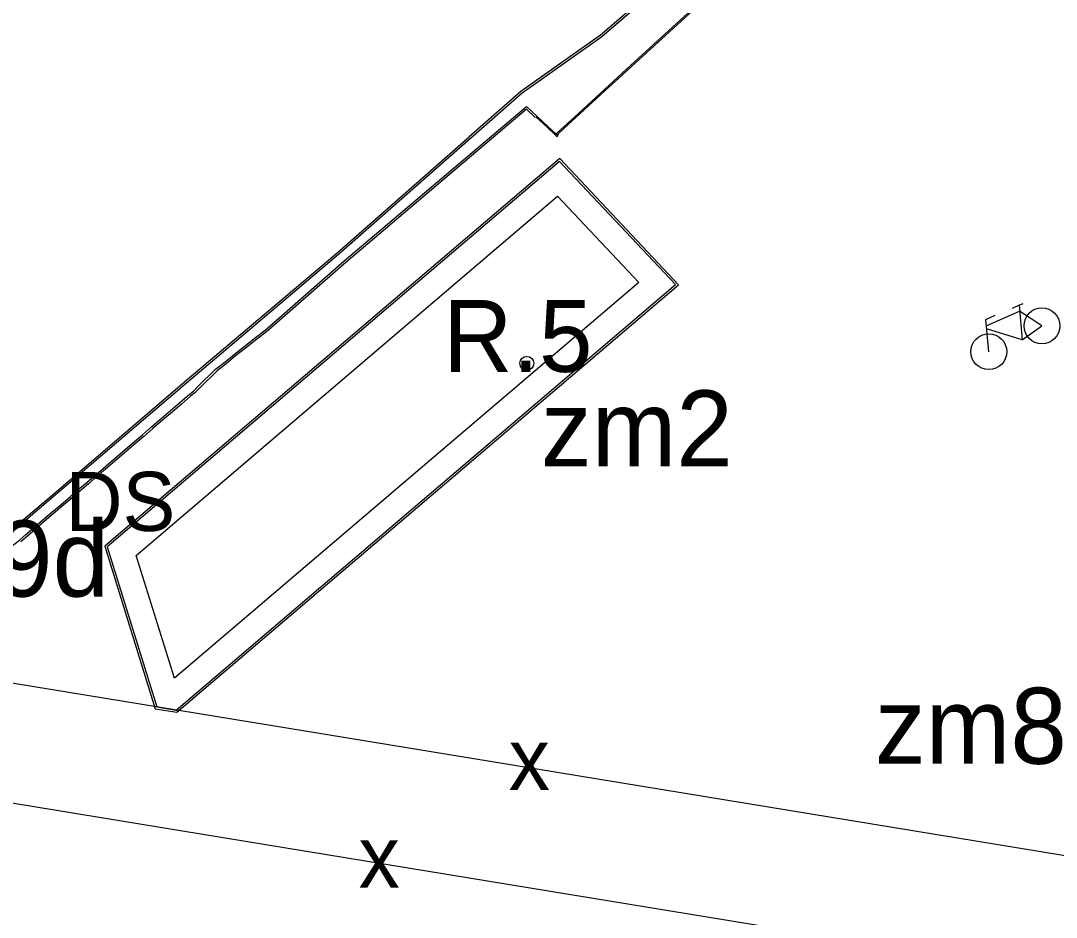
# Model space of a CAD drawing. Extents: x -555070 to -553076, y -1186731 to -1182766.
# Drawn here: x -554659.4 to -554414.1, y -1185500.5 to -1185288.2 of the extents above; entities that cross this region are included whole.
import ezdxf

# ---------------------------------------------------------------- set-up
doc = ezdxf.new("R2010")
doc.units = 0
for name, color, linetype in [('CYKLISTI_stav', 7, 'Continuous'), ('HRANICE_ZMENY_DO_KOO', 7, 'Continuous'), ('Level 10', 7, 'Continuous'), ('Level 13', 7, 'Continuous'), ('Level 29', 7, 'Continuous'), ('Level 4', 7, 'Continuous'), ('Level 46', 7, 'Continuous'), ('Level 59', 7, 'Continuous'), ('OBRYS_PLOCH', 7, 'Continuous'), ('rezerva_BV', 7, 'Continuous'), ('stav_DS', 7, 'Continuous')]:
    doc.layers.add(name, color=color, linetype=linetype)

msp = doc.modelspace()

# ---------------------------------------------------------------- linework, layer by layer
at = {"layer": 'CYKLISTI_stav'}
for p, q in [((-554422.93, -1185355.56), (-554424.57, -1185356.33)), ((-554422.93, -1185355.56), (-554422.02, -1185355.16)), ((-554422.93, -1185355.56), (-554422.24, -1185363.73)), ((-554430.86, -1185358.95), (-554428.64, -1185357.93)), ((-554430.13, -1185366.55), (-554430.86, -1185358.95)), ((-554430.72, -1185360.44), (-554422.82, -1185356.93)), ((-554417.54, -1185360.43), (-554422.82, -1185356.93)), ((-554422.24, -1185363.73), (-554430.65, -1185361.15)), ((-554422.24, -1185363.73), (-554417.54, -1185360.43))]:
    msp.add_line(p, q, dxfattribs=at)
for centre in [(-554417.54, -1185360.43), (-554430.13, -1185366.55)]:
    msp.add_circle(centre, 4.25, dxfattribs=at)
at = {"layer": 'HRANICE_ZMENY_DO_KOO'}
for p, q in [((-554497.69, -1185270.65), (-554522.05, -1185291.6)), ((-554522.05, -1185291.6), (-554540.91, -1185304.97)), ((-554540.91, -1185304.97), (-554553.18, -1185315.71)), ((-554539.64, -1185309.13), (-554582.42, -1185345.45)), ((-554537.54, -1185311.08), (-554539.64, -1185309.13)), ((-554584.48, -1185343.12), (-554553.18, -1185315.71)), ((-554620.48, -1185373.63), (-554584.48, -1185343.12)), ((-554582.42, -1185345.45), (-554601.2, -1185361.87)), ((-554603.5, -1185363.59), (-554606.15, -1185365.72)), ((-554601.2, -1185361.87), (-554603.5, -1185363.59)), ((-554606.15, -1185365.72), (-554608.48, -1185367.51)), ((-554608.48, -1185367.51), (-554610.74, -1185369.4)), ((-554612.89, -1185371.08), (-554616.97, -1185375.08)), ((-554610.74, -1185369.4), (-554612.89, -1185371.08)), ((-554650.96, -1185399.7), (-554620.48, -1185373.63)), ((-554618.16, -1185376.25), (-554619.15, -1185377.1)), ((-554616.97, -1185375.08), (-554618.16, -1185376.25)), ((-554619.15, -1185377.1), (-554621.34, -1185378.97)), ((-554623.55, -1185380.87), (-554625.78, -1185382.78)), ((-554621.34, -1185378.97), (-554623.55, -1185380.87)), ((-554625.78, -1185382.78), (-554628.06, -1185384.72)), ((-554628.06, -1185384.72), (-554630.26, -1185386.6)), ((-554632.58, -1185388.59), (-554634.89, -1185390.58)), ((-554630.26, -1185386.6), (-554632.58, -1185388.59)), ((-554634.89, -1185390.58), (-554638.83, -1185393.94)), ((-554638.83, -1185393.94), (-554641.3, -1185396.06)), ((-554643.35, -1185397.82), (-554645.42, -1185399.59)), ((-554641.3, -1185396.06), (-554643.35, -1185397.82)), ((-554662.18, -1185409.19), (-554650.96, -1185399.7)), ((-554645.42, -1185399.59), (-554647.3, -1185401.2)), ((-554649.6, -1185403.16), (-554651.7, -1185404.96)), ((-554647.3, -1185401.2), (-554649.6, -1185403.16)), ((-554651.7, -1185404.96), (-554653.79, -1185406.76)), ((-554653.79, -1185406.76), (-554655.81, -1185408.47)), ((-554657.81, -1185410.19), (-554659.38, -1185411.54)), ((-554655.81, -1185408.47), (-554657.81, -1185410.19))]:
    msp.add_line(p, q, dxfattribs=at)
msp.add_lwpolyline([(-554537.4, -1185310.93), (-554534.73, -1185313.41), (-554532.82, -1185315.19), (-554532.31, -1185315.67), (-554532.05, -1185314.87), (-554529.73, -1185312.74), (-554527.04, -1185310.28), (-554524.01, -1185307.5), (-554520.98, -1185304.73), (-554517.74, -1185301.76), (-554514.76, -1185299.04), (-554501.19, -1185286.63), (-554500.05, -1185285.59), (-554483.01, -1185271.32), (-554467.44, -1185258.63), (-554452.63, -1185246.62), (-554445.86, -1185240.54), (-554433.11, -1185229.16), (-554430.24, -1185228.1), (-554425.89, -1185227.65), (-554422.67, -1185227.83), (-554416.8, -1185229.06), (-554414.23, -1185229.78)], dxfattribs=at)
msp.add_lwpolyline([(-554503.58, -1185350.68), (-554531.74, -1185320.8), (-554639.5, -1185412.62), (-554627.57, -1185451.08), (-554622.41, -1185451.92)], close=True, dxfattribs=at)
at = {"layer": 'Level 13'}
for p, q in [((-554531.78, -1185321.49), (-554638.92, -1185412.79)), ((-554504.31, -1185350.64), (-554531.78, -1185321.49)), ((-554622.56, -1185451.39), (-554504.31, -1185350.64))]:
    msp.add_line(p, q, dxfattribs=at)
msp.add_lwpolyline([(-554638.92, -1185412.79), (-554627.18, -1185450.64), (-554622.56, -1185451.39)], dxfattribs=at)
at = {"layer": 'Level 29'}
for points in [[(-554293.2, -1185505.39), (-554587.17, -1185457.18), (-554869.52, -1185410.99), (-555057.83, -1185309.87), (-555060.53, -1185308.42)], [(-555065.37, -1185337.55), (-554878.61, -1185437.76), (-554591.7, -1185484.82), (-554218.96, -1185545.93), (-553901.49, -1185597.94), (-553620.76, -1185643.99), (-553313.81, -1185694.25), (-553085.95, -1185731.63)]]:
    msp.add_lwpolyline(points, dxfattribs=at)
at = {"layer": 'Level 4'}
msp.add_circle((-554539.54, -1185369.3), 1.64, dxfattribs=at)
at = {"layer": 'OBRYS_PLOCH'}
for p, q in [((-554521.74, -1185291.99), (-554540.6, -1185305.36)), ((-554582.75, -1185345.07), (-554539.62, -1185308.46)), ((-554539.62, -1185308.46), (-554537.2, -1185310.71)), ((-554537.2, -1185310.71), (-554534.53, -1185313.19)), ((-554534.53, -1185313.19), (-554532.62, -1185314.97)), ((-554532.62, -1185314.97), (-554532.45, -1185315.13)), ((-554601.51, -1185361.48), (-554582.75, -1185345.07)), ((-554603.81, -1185363.19), (-554601.51, -1185361.48)), ((-554613.22, -1185370.7), (-554611.05, -1185369.01)), ((-554621.67, -1185378.59), (-554619.48, -1185376.72)), ((-554635.22, -1185390.2), (-554632.91, -1185388.21)), ((-554639.15, -1185393.56), (-554635.22, -1185390.2)), ((-554641.63, -1185395.68), (-554639.15, -1185393.56)), ((-554649.92, -1185402.78), (-554647.63, -1185400.82)), ((-554647.63, -1185400.82), (-554645.75, -1185399.21))]:
    msp.add_line(p, q, dxfattribs=at)
for points in [[(-554468.69, -1185246.34), (-554489.84, -1185263.62), (-554497.35, -1185271.02), (-554521.74, -1185291.99)], [(-554532.45, -1185315.13), (-554532.31, -1185314.7), (-554529.93, -1185312.52), (-554527.24, -1185310.06), (-554524.21, -1185307.28), (-554521.18, -1185304.51), (-554517.94, -1185301.54), (-554514.96, -1185298.82), (-554501.39, -1185286.41), (-554500.25, -1185285.36), (-554483.2, -1185271.09)], [(-554540.6, -1185305.36), (-554552.85, -1185316.09), (-554584.15, -1185343.5), (-554620.16, -1185374.01)], [(-554611.05, -1185369.01), (-554608.79, -1185367.12), (-554606.46, -1185365.33), (-554603.81, -1185363.19)], [(-554619.48, -1185376.72), (-554618.5, -1185375.88), (-554617.32, -1185374.72), (-554613.22, -1185370.7)], [(-554620.16, -1185374.01), (-554650.64, -1185400.08), (-554661.85, -1185409.57)], [(-554626.11, -1185382.4), (-554623.88, -1185380.49), (-554621.67, -1185378.59)], [(-554632.91, -1185388.21), (-554630.58, -1185386.22), (-554628.38, -1185384.34), (-554626.11, -1185382.4)], [(-554645.75, -1185399.21), (-554643.68, -1185397.44), (-554641.63, -1185395.68)], [(-554654.12, -1185406.38), (-554652.03, -1185404.58), (-554649.92, -1185402.78)], [(-554658.14, -1185409.81), (-554656.13, -1185408.09), (-554654.12, -1185406.38)], [(-554663.8, -1185414.32), (-554661.71, -1185412.73), (-554659.7, -1185411.15), (-554658.14, -1185409.81)]]:
    msp.add_lwpolyline(points, dxfattribs=at)
at = {"layer": 'rezerva_BV'}
for p, q in [((-554531.78, -1185321.49), (-554638.92, -1185412.79)), ((-554531.78, -1185321.49), (-554638.92, -1185412.79)), ((-554504.31, -1185350.64), (-554531.78, -1185321.49)), ((-554504.31, -1185350.64), (-554531.78, -1185321.49)), ((-554622.56, -1185451.39), (-554504.31, -1185350.64)), ((-554622.56, -1185451.39), (-554504.31, -1185350.64))]:
    msp.add_line(p, q, dxfattribs=at)
for points in [[(-554622.99, -1185443.89), (-554632.02, -1185414.79), (-554532.23, -1185329.76), (-554513, -1185350.16), (-554622.99, -1185443.89)], [(-554638.92, -1185412.79), (-554627.18, -1185450.64), (-554622.56, -1185451.39)], [(-554638.92, -1185412.79), (-554627.18, -1185450.64), (-554622.56, -1185451.39)]]:
    msp.add_lwpolyline(points, dxfattribs=at)
at = {"layer": 'stav_DS'}
for p, q in [((-554521.74, -1185291.99), (-554540.6, -1185305.36)), ((-554582.75, -1185345.07), (-554539.62, -1185308.46)), ((-554539.62, -1185308.46), (-554537.2, -1185310.71)), ((-554537.2, -1185310.71), (-554534.53, -1185313.19)), ((-554534.53, -1185313.19), (-554532.62, -1185314.97)), ((-554532.62, -1185314.97), (-554532.45, -1185315.13)), ((-554601.51, -1185361.48), (-554582.75, -1185345.07)), ((-554603.81, -1185363.19), (-554601.51, -1185361.48)), ((-554613.22, -1185370.7), (-554611.05, -1185369.01)), ((-554621.67, -1185378.59), (-554619.48, -1185376.72)), ((-554635.22, -1185390.2), (-554632.91, -1185388.21)), ((-554639.15, -1185393.56), (-554635.22, -1185390.2)), ((-554641.63, -1185395.68), (-554639.15, -1185393.56)), ((-554649.92, -1185402.78), (-554647.63, -1185400.82)), ((-554647.63, -1185400.82), (-554645.75, -1185399.21))]:
    msp.add_line(p, q, dxfattribs=at)
for points in [[(-554468.69, -1185246.34), (-554489.84, -1185263.62), (-554497.35, -1185271.02), (-554521.74, -1185291.99)], [(-554532.45, -1185315.13), (-554532.31, -1185314.7), (-554529.93, -1185312.52), (-554527.24, -1185310.06), (-554524.21, -1185307.28), (-554521.18, -1185304.51), (-554517.94, -1185301.54), (-554514.96, -1185298.82), (-554501.39, -1185286.41), (-554500.25, -1185285.36), (-554483.2, -1185271.09)], [(-554540.6, -1185305.36), (-554552.85, -1185316.09), (-554584.15, -1185343.5), (-554620.16, -1185374.01)], [(-554611.05, -1185369.01), (-554608.79, -1185367.12), (-554606.46, -1185365.33), (-554603.81, -1185363.19)], [(-554619.48, -1185376.72), (-554618.5, -1185375.88), (-554617.32, -1185374.72), (-554613.22, -1185370.7)], [(-554620.16, -1185374.01), (-554650.64, -1185400.08), (-554661.85, -1185409.57)], [(-554626.11, -1185382.4), (-554623.88, -1185380.49), (-554621.67, -1185378.59)], [(-554632.91, -1185388.21), (-554630.58, -1185386.22), (-554628.38, -1185384.34), (-554626.11, -1185382.4)], [(-554645.75, -1185399.21), (-554643.68, -1185397.44), (-554641.63, -1185395.68)], [(-554654.12, -1185406.38), (-554652.03, -1185404.58), (-554649.92, -1185402.78)], [(-554658.14, -1185409.81), (-554656.13, -1185408.09), (-554654.12, -1185406.38)], [(-554663.8, -1185414.32), (-554661.71, -1185412.73), (-554659.7, -1185411.15), (-554658.14, -1185409.81)]]:
    msp.add_lwpolyline(points, dxfattribs=at)

# ---------------------------------------------------------------- texts
at = {"layer": 'Level 10'}
for s, p in [('zm2', (-554536.21, -1185393.72)), ('zm9d', (-554697.31, -1185424.53)), ('zm8d', (-554457.1, -1185464.13))]:
    msp.add_text(s, height=18, dxfattribs=at).set_placement(p)
at = {"layer": 'Level 29'}
for p in [(-554543.83, -1185470.33), (-554579.38, -1185493.49)]:
    msp.add_text('x', height=14.62, rotation=0.008, dxfattribs=at).set_placement(p)
at = {"layer": 'Level 46'}
msp.add_text('R.5', height=17, dxfattribs=at).set_placement((-554559.36, -1185371.32))
at = {"layer": 'Level 59'}
msp.add_text('DS', height=14, dxfattribs=at).set_placement((-554648.78, -1185409))

doc.saveas('drawing.dxf')
